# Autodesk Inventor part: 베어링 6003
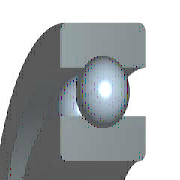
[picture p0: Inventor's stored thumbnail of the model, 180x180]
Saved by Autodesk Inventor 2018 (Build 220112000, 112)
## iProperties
Created: 2012-02
Part Number: 베어링 6003
Material: 강철, 연강
Description: 깊은 그루브 볼 베어링
Document SubType Name: Modeling
Standard: KS B 2023
Designer: mduedu
Standards Organization: KS
Language: ko-KR
Size Designation: 6003 - 17 x 35 x 10
Categories: <MemberInstance><Categories><Category DisplayName="샤프트 부품" InternalName="7f7aeb1f-a693-4053-b835-cee3144e0d98" Mnemonic="SHFT"><Category DisplayName="베어링" Inter
Density: 1 g/cm^3
Appearance: 노란색
IsCustomPart: 1
Author: mduedu
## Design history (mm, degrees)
sketch "스케치" dims "d0" = 4.68 (= -0.26 x WD + 0.26 x BD)
  geometry: L1 (2.66, 13)-(7.34, 13); L2 (5, 13)-(5, 10.66); L3 (5, 13)-(5, 15.34); L4 (3.261, 11.434)-(0, 11.434); L5 (0, 8.5)-(10, 8.5); L6 (3.261, 14.566)-(0, 14.566); L7 (0, 17.5)-(10, 17.5); L8 (10, 8.5)-(10, 11.434); L9 (6.739, 11.434)-(10, 11.434); L10 (6.739, 14.566)-(10, 14.566); L11 (10, 17.5)-(10, 14.566); L12 (-1.4, 0)-(8.4, 0) reference; L13 (0, -0.3)-(0, 5.3) reference
  constraints: 22 end point, 4 point on line, 2 collinear, 2 perpendicular, 2 symmetric about line, 1 midpoint, 1 parallel, 14 other
  dimensions: "d9" = 17 diameter of L5 L12 (= WD); "d11" = 35 diameter of L7 L12 (= BD); "d12" = 10 distance between parallel lines of L8 L13 (= KB); "d13" = 22.868 diameter of L9 L12 (= 0.326 x BD + 0.674 x WD)
revolve "본체" stored, may be unused: angle "d6" = 90 deg
revolve "볼" stored, may be unused: angle "d7" = 90 deg
pattern_circular "IDS_ARRAYBALL[SIMPL:T]" dims angle "d3" = 360 deg
body "Solid1"
fillet "모깎기1" dims "d1" = 0.3 (= KRS)
other parameters: "WD" = 17 [user parameter; used in 5 equation terms], "BD" = 35 [user parameter; used in 5 equation terms], "KB" = 10 [user parameter; used in 1 equation term], "KRS" = 0.3 [user parameter; used in 1 equation term], "d4" = 0, "d5" = 0, "d8" = 0, "d14" = 0, "d15" = 0, "BBA" = 0 [user parameter], "BC0" = 3250000 [user parameter], "BC" = 6050000 [user parameter], "BR" = 17.5 (= 0.5 x BD) [user parameter], "WR" = 8.5 (= 0.5 x WD) [user parameter]
